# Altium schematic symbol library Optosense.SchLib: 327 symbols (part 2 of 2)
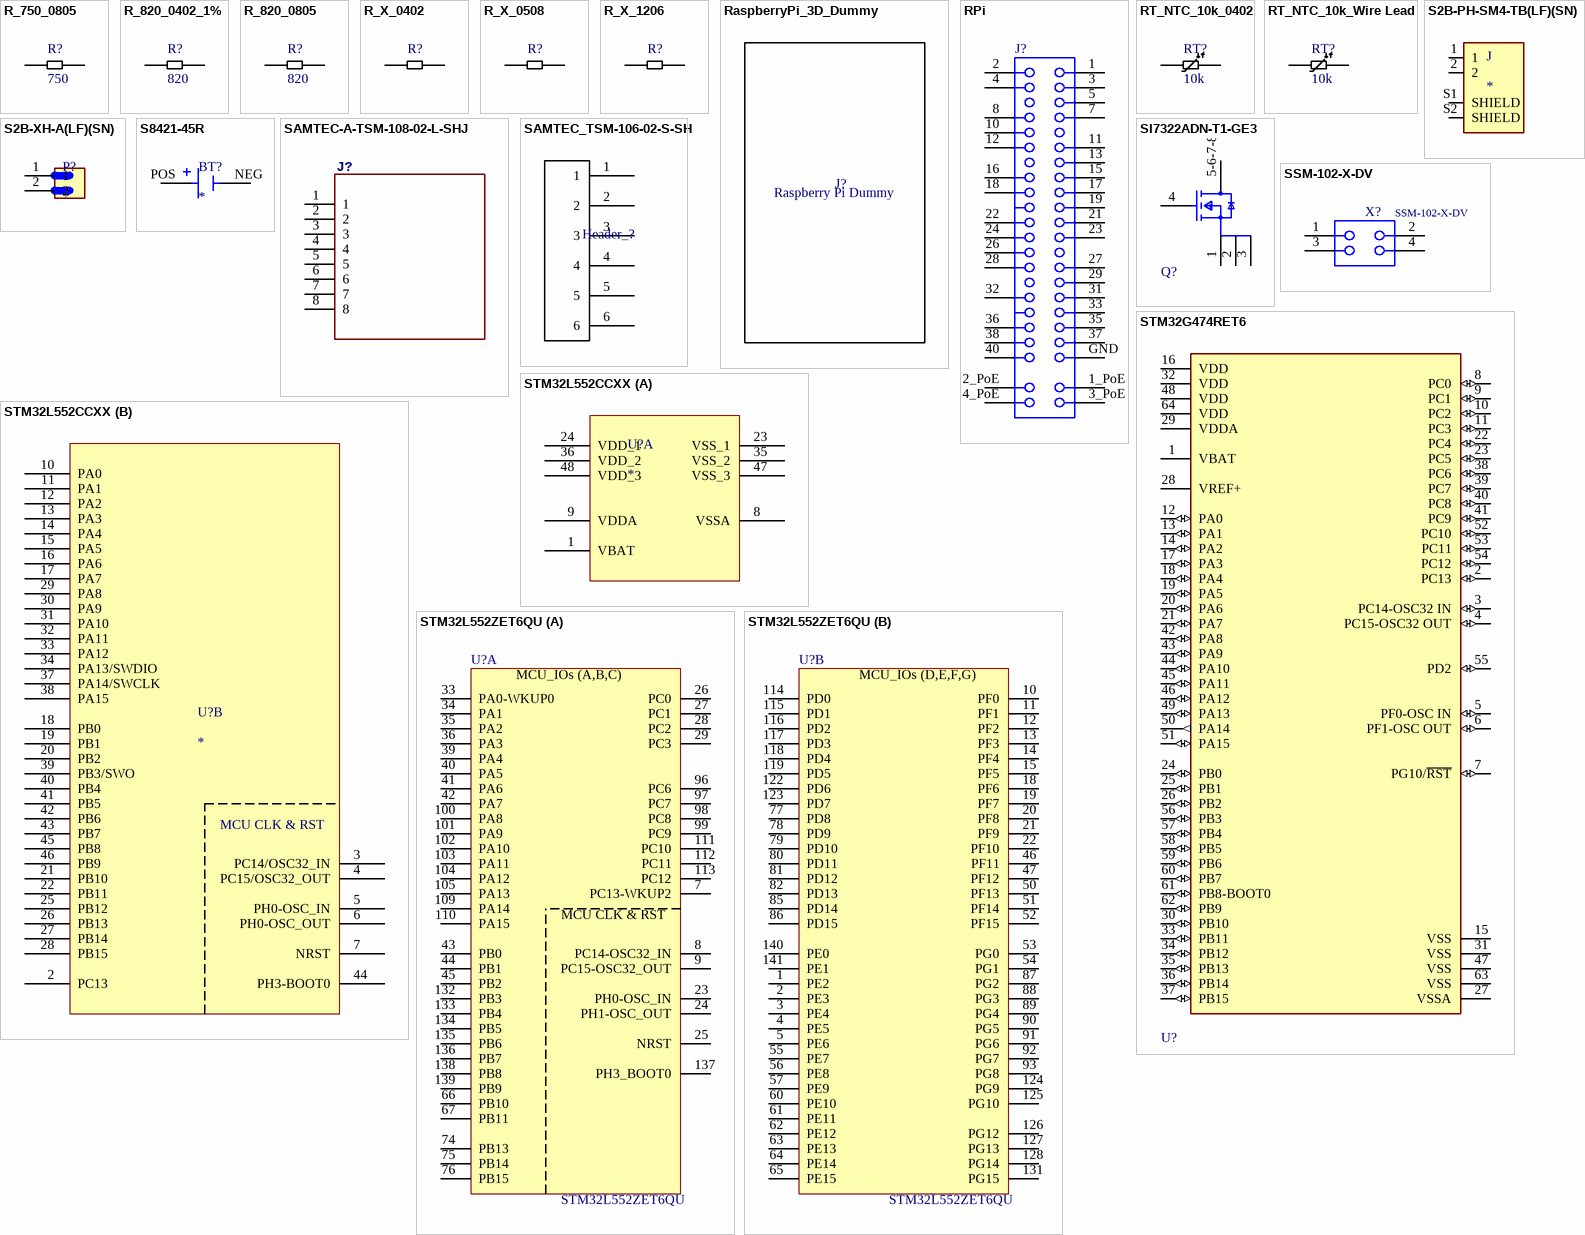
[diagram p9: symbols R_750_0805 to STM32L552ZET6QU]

## R_820_0402_1%
designator R?, comment 820
CRCW0402820RFKED
footprint R_0402
pins: 1 (power), 2 (power)

## R_820_0805
designator R?, comment 820
ERJ-6GEYJ821V
footprint R_0805
pins: 1 (power), 2 (power)

## R_X_0402
designator R?
footprint R_0402
pins: 1 (power), 2 (power)

## R_X_0508
designator R?
footprint R_0508_reversed
pins: 1 (power), 2 (power)

## R_X_1206
designator R?
footprint R_1206
pins: 1 (power), 2 (power)

## RaspberryPi_3D_Dummy
designator J?
WR-PHD Socket Header, SMT, pitch 2.54mm, Dual Row, Vertical, 40pin; Part Number: 61004021821; Pin Number: 40; Gender: Female; Rated Current: 3A; Working Voltage: 250VAC; Withstanding Voltage: 600VAC; Contact Resistance: 20mOhm
footprint RPi (Socket Header, Pitch 2.54 mm, SMT, Vertical, dual row, 40p)

## RPi
designator J?
WR-PHD Socket Header, SMT, pitch 2.54mm, Dual Row, Vertical, 40pin; Part Number: 61004021821; Pin Number: 40; Gender: Female; Rated Current: 3A; Working Voltage: 250VAC; Withstanding Voltage: 600VAC; Contact Resistance: 20mOhm
footprint RPi - THT Hybrid (Socket Header, Pitch 2.54 mm, SMT, Vertical, dual row, 40p)
footprint RPi - PoE Hole (Socket Header, Pitch 2.54 mm, SMT, Vertical, dual row, 40p)
footprint RPi - MountHole (Socket Header, Pitch 2.54 mm, SMT, Vertical, dual row, 40p)
pins: 1, 1_PoE, 2, 2_PoE, 3, 3_PoE, 4, 4_PoE, 5, 7, 8, 10, 11, 12, 13, 15, 16, 17, 18, 19, 21, 22, 23, 24, 26, 27, 28, 29, 31, 32, 33, 35, 36, 37, 38, 40, GND

## RT_NTC_10k_0402
designator RT?, comment 10k
NTCG103JF103FT1
footprint R_0402
pins: 1 (power), 2 (power)

## RT_NTC_10k_Wire Lead
designator RT?, comment 10k
NTCALUG01A103F161L
footprint RT_Via (NTCALUG01A103F161L)
pins: 1 (power), 2 (power)

## S2B-PH-SM4-TB(LF)(SN)
designator J
Connector Header Surface Mount, Right Angle 2 position 0.079 _2.00mm_; MP: S2B-PH-SM4-TB_LF__SN_; MF: JST Sales
footprint JST_S2B-PH-SM4-TB(LF)(SN)
pins: 1, 2, S1 SHIELD, S2 SHIELD

## S2B-XH-A(LF)(SN)
designator P?
Connector Header Through Hole, Right Angle 2 position 0.098 (2.50mm); MP: S2B-XH-A(LF)(SN); MF: JST Sales
footprint JST_S2B-XH-A(LF)(SN)
pins: 1, 2

## S8421-45R
designator BT?
Battery Holder (Open) Coin, 20.0mm 1 Cell SMD (SMT) Tab; MF: Harwin Inc.; MP: S8421-45R
footprint BAT_S8421-45R
pins: NEG, POS

## SAMTEC-A-TSM-108-02-L-SHJ
designator J?
footprint SAMTEC-A-TSM-108-02-L-SH
pins: 1, 2, 3, 4, 5, 6, 7, 8

## SAMTEC_TSM-106-02-S-SH
designator Header_?
footprint SAMTEC_TSM-106-02-S-SH
pins: 1, 2, 3, 4, 5, 6

## SI7322ADN-T1-GE3
designator Q?  (value not drawn)
footprint Vishay_S16-2667-SINGLE_MFG
pins: 1 S, 2 S, 3 S, 4 G, 5-6-7-8 D

## SSM-102-X-DV
designator X?
footprint SAMTEC-SSM-102-X-DV
pins: 1, 2, 3, 4

## STM32G474RET6
designator U?  (value not drawn)
footprint STMicroelectronics_LQFP64-5W_IPC_A
pins: 1 VBAT (power), 2 PC13 (io), 3 PC14-OSC32 IN (io), 4 PC15-OSC32 OUT (io), 5 PF0-OSC IN (io), 6 PF1-OSC OUT (io), 7 PG10/~{RST} (io), 8 PC0 (io), 9 PC1 (io), 10 PC2 (io), 11 PC3 (io), 12 PA0 (io), 13 PA1 (io), 14 PA2 (io), 15 VSS (power), 16 VDD (power), 17 PA3 (io), 18 PA4 (io), 19 PA5 (io), 20 PA6 (io), 21 PA7 (io), 22 PC4 (io), 23 PC5 (io), 24 PB0 (io), 25 PB1 (io), 26 PB2 (io), 27 VSSA (power), 28 VREF+ (power), 29 VDDA (power), 30 PB10 (io), 31 VSS (power), 32 VDD (power), 33 PB11 (io), 34 PB12 (io), 35 PB13 (io), 36 PB14 (io), 37 PB15 (io), 38 PC6 (io), 39 PC7 (io), 40 PC8 (io), 41 PC9 (io), 42 PA8 (io), 43 PA9 (io), 44 PA10 (io), 45 PA11 (io), 46 PA12 (io), 47 VSS (power), 48 VDD (power), 49 PA13 (io), 50 PA14 (out), 51 PA15 (io), 52 PC10 (io), 53 PC11 (io), 54 PC12 (io), 55 PD2 (io), 56 PB3 (io), 57 PB4 (io), 58 PB5 (io), 59 PB6 (io), 60 PB7 (io), 61 PB8-BOOT0 (io), 62 PB9 (io), 63 VSS (power), 64 VDD (power)

## STM32L552CCXX
designator U?
footprint LQFP-48 (LQFP-48, 48-Leads, Body 6,90x6,90mm, Pitch 0,50mm, IPC Medium Density)
part A pins: 1 VBAT, 8 VSSA, 9 VDDA, 23 VSS_1, 24 VDD_1, 35 VSS_2, 36 VDD_2, 47 VSS_3, 48 VDD_3
part B pins: 2 PC13, 3 PC14/OSC32_IN, 4 PC15/OSC32_OUT, 5 PH0-OSC_IN, 6 PH0-OSC_OUT, 7 NRST, 10 PA0, 11 PA1, 12 PA2, 13 PA3, 14 PA4, 15 PA5, 16 PA6, 17 PA7, 18 PB0, 19 PB1, 20 PB2, 21 PB10, 22 PB11, 25 PB12, 26 PB13, 27 PB14, 28 PB15, 29 PA8, 30 PA9, 31 PA10, 32 PA11, 33 PA12, 34 PA13/SWDIO, 37 PA14/SWCLK, 38 PA15, 39 PB3/SWO, 40 PB4, 41 PB5, 42 PB6, 43 PB7, 44 PH3-BOOT0, 45 PB8, 46 PB9

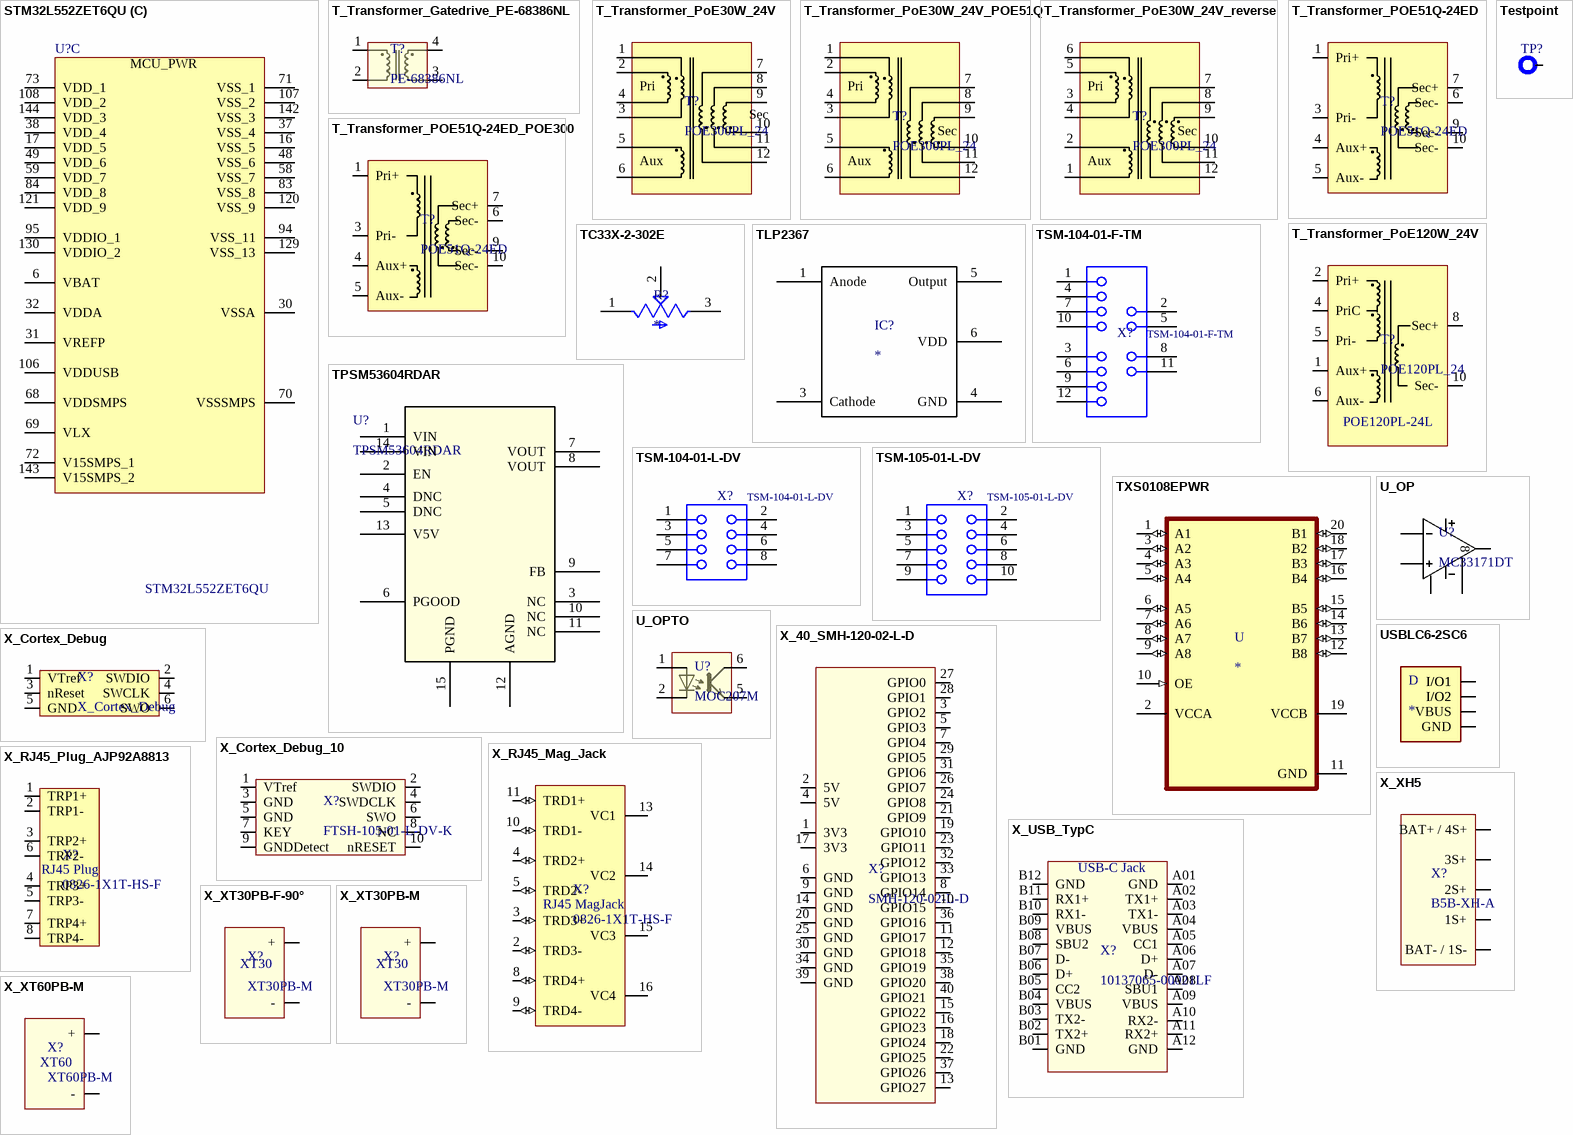
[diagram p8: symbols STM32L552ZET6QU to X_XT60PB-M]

## STM32L552ZET6QU
designator U?
STM32L552ZET6Q MCU,LQFP144 20x20, 0.5, no AES, Q for Int SMPS; Internal_Part_Number: MCD-01055; Part_Type: IC; Manufacturer: STMICROELECTRONICS; BMS_Part_Number: 9175310; ECCN_US: 3A991A2; ECCN_EU: NEC; Provided_By: SUBCO with ST control
footprint *QFP50P2200X2200X160-144N
part A pins: 7 PC13-WKUP2, 8 PC14-OSC32_IN, 9 PC15-OSC32_OUT, 23 PH0-OSC_IN, 24 PH1-OSC_OUT, 25 NRST, 26 PC0, 27 PC1, 28 PC2, 29 PC3, 33 PA0-WKUP0, 34 PA1, 35 PA2, 36 PA3, 39 PA4, 40 PA5, 41 PA6, 42 PA7, 43 PB0, 44 PB1, 45 PB2, 66 PB10, 67 PB11, 74 PB13, 75 PB14, 76 PB15, 96 PC6, 97 PC7, 98 PC8, 99 PC9, 100 PA8, 101 PA9, 102 PA10, 103 PA11, 104 PA12, 105 PA13, 109 PA14, 110 PA15, 111 PC10, 112 PC11, 113 PC12, 132 PB3, 133 PB4, 134 PB5, 135 PB6, 136 PB7, 137 PH3_BOOT0, 138 PB8, 139 PB9
part B pins: 1 PE2, 2 PE3, 3 PE4, 4 PE5, 5 PE6, 10 PF0, 11 PF1, 12 PF2, 13 PF3, 14 PF4, 15 PF5, 18 PF6, 19 PF7, 20 PF8, 21 PF9, 22 PF10, 46 PF11, 47 PF12, 50 PF13, 51 PF14, 52 PF15, 53 PG0, 54 PG1, 55 PE7, 56 PE8, 57 PE9, 60 PE10, 61 PE11, 62 PE12, 63 PE13, 64 PE14, 65 PE15, 77 PD8, 78 PD9, 79 PD10, 80 PD11, 81 PD12, 82 PD13, 85 PD14, 86 PD15, 87 PG2, 88 PG3, 89 PG4, 90 PG5, 91 PG6, 92 PG7, 93 PG8, 114 PD0, 115 PD1, 116 PD2, 117 PD3, 118 PD4, 119 PD5, 122 PD6, 123 PD7, 124 PG9, 125 PG10, 126 PG12, 127 PG13, 128 PG14, 131 PG15, 140 PE0, 141 PE1
part C pins: 6 VBAT, 16 VSS_5, 17 VDD_5, 30 VSSA, 31 VREFP, 32 VDDA, 37 VSS_4, 38 VDD_4, 48 VSS_6, 49 VDD_6, 58 VSS_7, 59 VDD_7, 68 VDDSMPS, 69 VLX, 70 VSSSMPS, 71 VSS_1, 72 V15SMPS_1, 73 VDD_1, 83 VSS_8, 84 VDD_8, 94 VSS_11, 95 VDDIO_1, 106 VDDUSB, 107 VSS_2, 108 VDD_2, 120 VSS_9, 121 VDD_9, 129 VSS_13, 130 VDDIO_2, 142 VSS_3, 143 V15SMPS_2, 144 VDD_3

## T_Transformer_Gatedrive_PE-68386NL
designator T?, comment PE-68386NL
Transformer_Gatedrive_PE-68386NL
footprint T_PE-68386NL
pins: 1 (power), 2 (power), 3 (power), 4 (power)

## T_Transformer_PoE30W_24V
designator T?, comment POE300PL_24
Transformer_PoE_24V_30W
footprint Transformer_Coilcraft_POE300 (POE300F-24L)
pins: 1 (power), 2 (power), 3 (power), 4 (power), 5 (power), 6 (power), 7 (power), 8 (power), 9 (power), 10 (power), 11 (power), 12 (power)

## T_Transformer_PoE30W_24V_POE51Q
designator T?, comment POE300PL_24
Transformer_PoE_24V_30W
footprint Transformer_Coilcraft_POE300/POE51Q - duplicate (POE300F-24L)
pins: 1 (power), 2 (power), 3 (power), 4 (power), 5 (power), 6 (power), 7 (power), 8 (power), 9 (power), 10 (power), 11 (power), 12 (power)

## T_Transformer_PoE30W_24V_reverse
designator T?, comment POE300PL_24
Transformer_PoE_24V_30W
footprint Transformer_Coilcraft_POE300 - Reverse (POE300F-24L)
pins: 1 (power), 2 (power), 3 (power), 4 (power), 5 (power), 6 (power), 7 (power), 8 (power), 9 (power), 10 (power), 11 (power), 12 (power)

## T_Transformer_POE51Q-24ED
designator T?, comment POE51Q-24ED
Transformer_PoE_24V_51W
footprint POExxQ-24E (Coilcraft Flyback Transformer)
pins: 1 Pri+ (power), 3 Pri- (power), 4 Aux+ (power), 5 Aux- (power), 6 Sec- (power), 7 Sec+ (power), 9 Sec- (power), 10 Sec- (power)

## T_Transformer_POE51Q-24ED_POE300
designator T?, comment POE51Q-24ED
Transformer_PoE_24V_51W
footprint Transformer_Coilcraft_POE51Q/POE300 (POE300F-24L)
pins: 1 Pri+ (power), 3 Pri- (power), 4 Aux+ (power), 5 Aux- (power), 6 Sec- (power), 7 Sec+ (power), 9 Sec- (power), 10 Sec- (power)

## T_Transformer_PoE120W_24V
designator T?, comment POE120PL_24
Transformer_PoE_24V_120W
footprint Transformer_Coilcraft_POE120 (POE12PL-24)
pins: 1 Aux+ (power), 2 Pri+ (power), 4 PriC (power), 5 Pri- (power), 6 Aux- (power), 8 Sec+ (power), 10 Sec- (power)

## TC33X-2-302E
designator R?
3 kOhms 0.1W, 1/10W J Lead Surface Mount Trimmer Potentiometer Cermet 1 Turn Top Adjustment; MF: Bourns; MP: TC33X-2-302E
footprint TRIM_TC33X-2-302E
pins: 1 CCW, 2 W, 3 CW

## Testpoint
designator TP?, comment TP  (value not drawn)
Testpoint
footprint Testpoint
pins: 1

## TLP2367
designator IC?
footprint SOIC127P970X425-6N
pins: 1 Anode, 3 Cathode, 4 GND, 5 Output, 6 VDD

## TPSM53604RDAR
designator U?
No Description Available; SourceLibrary: TI_2020-03-16; Built_By: EMA_Cory; Vendor: Texas Instruments
footprint Texas_Instruments_RDA0015A_MFG
pins: 1 VIN (power), 2 EN, 3 NC, 4 DNC, 5 DNC, 6 PGOOD, 7 VOUT, 8 VOUT, 9 FB, 10 NC, 11 NC, 12 AGND, 13 V5V, 14 VIN (power), 15 PGND

## TSM-104-01-F-TM
designator X?
footprint TSM-104-01-F-TM
pins: 1, 2, 3, 4, 5, 6, 7, 8, 9, 10, 11, 12

## TSM-104-01-L-DV
designator X?
footprint SAMTEC-A-TSM-104-01-L-DV
pins: 1, 2, 3, 4, 5, 6, 7, 8

## TSM-105-01-L-DV
designator X?
footprint SAMTEC-A-TSM-105-01-L-DV
pins: 1, 2, 3, 4, 5, 6, 7, 8, 9, 10

## TXS0108EPWR
designator U
8-Bit Bidirectional Voltage-Level Shifter For Open-Drain And Push-Pull Application; MP: TXS0108EPWR; MF: Texas Instruments
footprint SOP65P640X120-20N
pins: 1 A1 (io), 2 VCCA (power), 3 A2 (io), 4 A3 (io), 5 A4 (io), 6 A5 (io), 7 A6 (io), 8 A7 (io), 9 A8 (io), 10 OE (in), 11 GND (power), 12 B8 (io), 13 B7 (io), 14 B6 (io), 15 B5 (io), 16 B4 (io), 17 B3 (io), 18 B2 (io), 19 VCCB (power), 20 B1 (io)

## U_OP
designator U?, comment MC33171DT
footprint SOIC-8
pins: 1 Offset Null (power), 2 Inverting Input (power), 3 Non-Inverting Input (power), 4 Vcc- (power), 5 Offset Null (power), 6 Output (power), 7 Vcc+ (power)

## U_OPTO
designator U?, comment MOC207M
OPTO
footprint SOIC-8
pins: 1 (power), 2 (power), 5 (power), 6 (power)

## USBLC6-2SC6
designator D
17V Clamp 5A _8/20Âµs_ Ipp Tvs Diode Surface Mount SOT-23-6; MP: USBLC6-2SC6; MF: STMicroelectronics
footprint SOT95P280X145-6N
pins: 1 I/O1, 2 GND (power), 3 I/O2, 4 I/O2, 5 VBUS (power), 6 I/O1

## X_40_SMH-120-02-L-D
designator X?, comment SMH-120-02-L-D
footprint X_Buchse_2,54mm_40_2Row_RightAngle
pins: 1 3V3 (power), 2 5V (power), 3 GPIO2 (io), 4 5V (power), 5 GPIO3 (io), 6 GND (power), 7 GPIO4 (io), 8 GPIO14 (io), 9 GND (power), 10 GPIO15 (io), 11 GPIO17 (io), 12 GPIO18 (io), 13 GPIO27 (io), 14 GND (power), 15 GPIO22 (io), 16 GPIO23 (io), 17 3V3 (power), 18 GPIO24 (io), 19 GPIO10 (io), 20 GND (power), 21 GPIO9 (io), 22 GPIO25 (io), 23 GPIO11 (io), 24 GPIO8 (io), 25 GND (power), 26 GPIO7 (io), 27 GPIO0 (io), 28 GPIO1 (io), 29 GPIO5 (io), 30 GND (power), 31 GPIO6 (io), 32 GPIO12 (io), 33 GPIO13 (io), 34 GND (power), 35 GPIO19 (io), 36 GPIO16 (io), 37 GPIO26 (io), 38 GPIO20 (io), 39 GND (power), 40 GPIO21 (io)

## X_Cortex_Debug
designator X?
Footprint
footprint Cortex_Debug
pins: 1 VTref (power), 2 SWDIO (io), 3 nReset (io), 4 SWCLK (io), 5 GND (power), 6 SWO (io)

## X_Cortex_Debug_10
designator X?, comment FTSH-105-01-L-DV-K
footprint SAMTEC_FTSH-105-01-L-DV-K
pins: 1 VTref (power), 2 SWDIO, 3 GND (power), 4 SWDCLK, 5 GND (power), 6 SWO, 7 KEY (power), 8 NC, 9 GNDDetect (power), 10 nRESET

## X_RJ45_Mag_Jack
designator X?, comment 0826-1X1T-HS-F
RJ45 Magnetic Jack with Transformer
footprint RJ45_magjack (0826-1X1T-HS-F)
pins: 2 TRD3- (io), 3 TRD3+ (io), 4 TRD2+ (io), 5 TRD2- (io), 8 TRD4+ (io), 9 TRD4- (io), 10 TRD1- (io), 11 TRD1+ (io), 13 VC1 (power), 14 VC2 (power), 15 VC3 (power), 16 VC4 (power)

## X_RJ45_Plug_AJP92A8813
designator X?, comment 0826-1X1T-HS-F
AJP92A8813
footprint X_RJ45_Plug
pins: 1 TRP1+ (io), 2 TRP1- (io), 3 TRP2+ (io), 4 TRP3+ (io), 5 TRP3- (io), 6 TRP2- (io), 7 TRP4+ (io), 8 TRP4- (io)

## X_USB_TypC
designator X?, comment 10137065-00021LF
footprint X_USBC_JACK (10137065-00021LF)
pins: A01 GND (power), A02 TX1+ (io), A03 TX1- (io), A04 VBUS (power), A05 CC1 (io), A06 D+ (io), A07 D- (io), A08 SBU1 (io), A09 VBUS (power), A10 RX2- (io), A11 RX2+ (io), A12 GND (power), B01 GND (power), B02 TX2+ (io), B03 TX2- (io), B04 VBUS (power), B05 CC2 (io), B06 D+ (io), B07 D- (io), B08 SBU2 (io), B09 VBUS (power), B10 RX1- (io), B11 RX1+ (io), B12 GND (power)

## X_XH5
designator X?, comment B5B-XH-A
footprint X_XH5
pins: 1 BAT- / 1S- (power), 2 1S+ (power), 3 2S+ (power), 4 3S+ (power), 5 BAT+ / 4S+ (power)

## X_XT30PB-F-90°
designator X?, comment XT30PB-M
XT30PB-F-90°
footprint X_XT30_90°
pins: 1 + (power), 2 - (power)

## X_XT30PB-M
designator X?, comment XT30PB-M
footprint X_XT30 (XT30PB-M)
pins: 1 - (power), 2 + (power)

## X_XT60PB-M
designator X?, comment XT60PB-M
footprint X_XT60
pins: 1 - (power), 2 + (power)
